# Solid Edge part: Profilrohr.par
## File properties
Username: bmolnar
Dokumentum tartalom típus: 0
Author: bmolnar
Last saved by: bmolnar
Revision: 83
Sűrűség: 0,000 kg/m^3
Pontosság: 0,990
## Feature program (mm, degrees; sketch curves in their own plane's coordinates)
base feature "unnamed BaseFeature 1"
thread "unnamed Thread 1"
thread "Menet_2"  ThreadDepth = 7.5 mm
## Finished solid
Body 1: solid body, 121 faces, 264 edges, 140 vertices.
  Faces by surface: plane 78, cylinder 29, cone 10, torus 4
  Edges by curve: line 188, circle 68, curve on surface 6, intersection 2
Bounding box of the edges (mm; curved faces can reach further): 65.000 x 70.000 x 59.500, from (-32.5, -32.5, 0) to (32.5, 37.5, 59.5).
Cylindrical faces by radius (mm): R1.375 x2, R3.4 x4, R4.283 x4, R5.5 x8, R25 x1, R25.9 x2, R26.1 x2, R27.6 x2, R43 x4
Conical faces (half-angle, radius in mm at the cone's reference point): 30 deg R25.325 x2, 30 deg R26.1887 x2, 45 deg R4.533 x2, 45 deg R26.25 x2, 45 deg R26.35 x2
Toroidal faces (ring radius, tube radius in mm): R27.4 r0.2 x4
Planar faces by outward normal: +x 9, +y 11, +z 8, -x 9, -y 9, -z 8, oblique 24
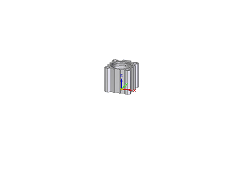
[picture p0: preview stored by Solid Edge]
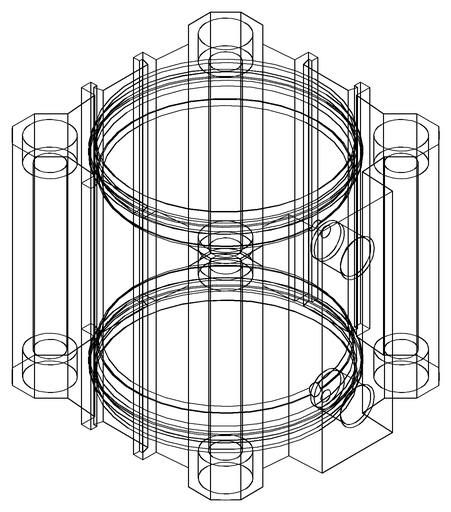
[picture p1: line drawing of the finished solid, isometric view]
